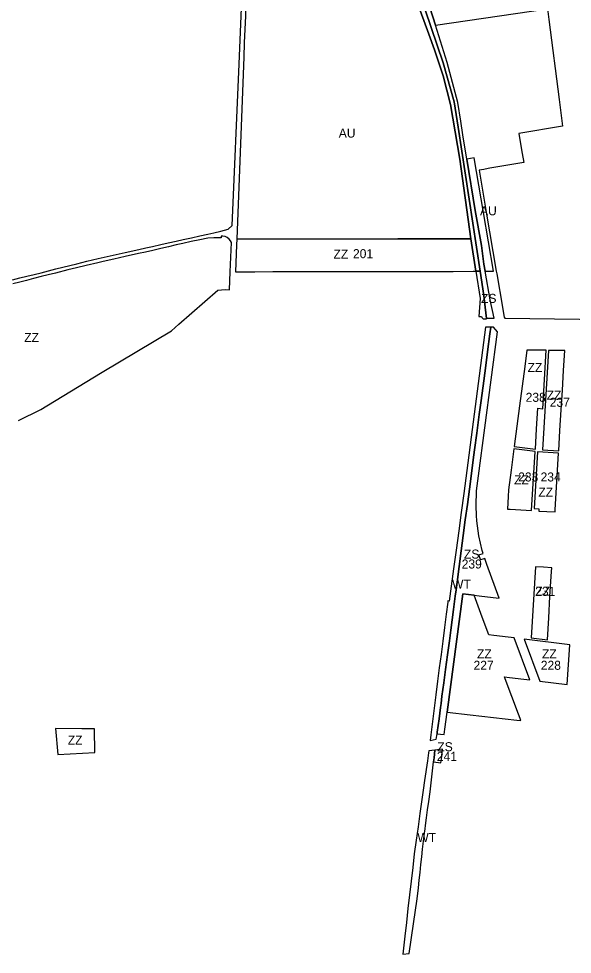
# Model space of a CAD drawing. Extents: x -521939 to -516426, y -1197857 to -1189551.
# Drawn here: x -519936 to -519323, y -1191680 to -1190643 of the extents above; entities that cross this region are included whole.
import ezdxf

# ---------------------------------------------------------------- set-up
doc = ezdxf.new("R2010")
doc.units = 0
for name, color, linetype in [('90640013', 7, 'Continuous'), ('90660013', 7, 'Continuous'), ('90660023', 7, 'Continuous'), ('90670013', 7, 'Continuous'), ('90670023', 7, 'Continuous'), ('90710013', 7, 'Continuous'), ('90750013', 7, 'Continuous'), ('ID_navrh', 7, 'Continuous')]:
    doc.layers.add(name, color=color, linetype=linetype)

msp = doc.modelspace()

# ---------------------------------------------------------------- linework, layer by layer
at = {"layer": '90640013'}
for points in [[(-519512.13, -1190554.9), (-519465.6, -1190691.56), (-519453.62, -1190734.65), (-519449.03, -1190762.69), (-519424.89, -1190922.71), (-519420.85, -1190949.46), (-519419.21, -1190962.53), (-519417.66, -1190974.95), (-519417.62, -1190974.6), (-519409.21, -1190974.7)], [(-519409.21, -1190974.7), (-519413.53, -1190954.2), (-519419.2, -1190922.7), (-519420.59, -1190914.95), (-519423.23, -1190894), (-519430.27, -1190855.42), (-519439.5, -1190798.18), (-519443.82, -1190771.36), (-519446.26, -1190756.2), (-519449.61, -1190735.43), (-519461.43, -1190691.22), (-519474.2, -1190649.71), (-519490.33, -1190599.63)], [(-519418.92, -1190984.59), (-519442.95, -1191169.26), (-519445.69, -1191190.31), (-519448.24, -1191210.54), (-519451.44, -1191231.94), (-519454.5, -1191252.76), (-519457.65, -1191277.52), (-519459.03, -1191288.5), (-519460.46, -1191288.31), (-519460.65, -1191289.8), (-519462.36, -1191303.03), (-519464.29, -1191317.96), (-519466.22, -1191332.83), (-519468.14, -1191347.66), (-519470.07, -1191362.61), (-519471.98, -1191377.42), (-519473.9, -1191392.31), (-519475.83, -1191407.23), (-519477.63, -1191422.05), (-519479.54, -1191436.95), (-519480.3, -1191443.11), (-519473.41, -1191441.72), (-519473.18, -1191440.03), (-519472.77, -1191437.09), (-519472.58, -1191435.69), (-519472.32, -1191433.7), (-519470.37, -1191418.91), (-519468.71, -1191406.36), (-519468.15, -1191402.09), (-519467.09, -1191394.09), (-519465.11, -1191379.15), (-519463.15, -1191364.31), (-519461, -1191348.01), (-519458.94, -1191332.49), (-519457.39, -1191320.76), (-519454.38, -1191298), (-519452.43, -1191283.22), (-519451.46, -1191275.9), (-519450.34, -1191267.46), (-519448.07, -1191250.27), (-519445.75, -1191232.74), (-519443.51, -1191215.75), (-519441.23, -1191198.47), (-519438.99, -1191181.55), (-519436.7, -1191164.25), (-519434.43, -1191147.07), (-519432.39, -1191131.65), (-519430.97, -1191120.9), (-519428.51, -1191102.27), (-519425.76, -1191081.47), (-519424.05, -1191068.52), (-519421.56, -1191049.69), (-519418.96, -1191030.07), (-519416.58, -1191012.09), (-519413.94, -1190992.07), (-519412.96, -1190984.66), (-519418.92, -1190984.59)], [(-519481.79, -1191510.66), (-519480.11, -1191500.2), (-519476.39, -1191466.96), (-519475.89, -1191462.49), (-519474.91, -1191453.7), (-519481.78, -1191454.44), (-519481.98, -1191456.8), (-519483.25, -1191465.69), (-519486.37, -1191487.58), (-519487.87, -1191498.12), (-519489.37, -1191508.66), (-519491.56, -1191524), (-519493.61, -1191538.9), (-519495.77, -1191553.8), (-519497.82, -1191568.74), (-519499.58, -1191583.93), (-519501.26, -1191598.96), (-519503.13, -1191614.19), (-519504.8, -1191629.42), (-519506.55, -1191644.93), (-519508.19, -1191660.16), (-519510.41, -1191680.24), (-519503.48, -1191679.19), (-519498.55, -1191646.53), (-519494.72, -1191618.59), (-519493.26, -1191606.37), (-519492.35, -1191598.05), (-519491.39, -1191589.35), (-519490.44, -1191580.74), (-519489.49, -1191572.1), (-519488.54, -1191563.47), (-519487.59, -1191554.84), (-519486.62, -1191546.07), (-519485.82, -1191540.95), (-519485.29, -1191537.48), (-519484.17, -1191528.9), (-519483.02, -1191520.08), (-519481.79, -1191510.66)]]:
    msp.add_lwpolyline(points, dxfattribs=at)
at = {"layer": '90660013'}
msp.add_lwpolyline([(-519424.76, -1190952.81), (-519426.07, -1190972.68), (-519423.35, -1190972.89), (-519423.05, -1190974.12), (-519421.6, -1190975.48), (-519417.75, -1190975.6), (-519417.58, -1190975.61), (-519417.66, -1190974.95), (-519419.21, -1190962.53), (-519420.85, -1190949.46), (-519424.89, -1190922.71), (-519429.49, -1190922.71), (-519424.76, -1190952.81)], dxfattribs=at)
at = {"layer": '90660023'}
for points in [[(-519461.41, -1191411.78), (-519444.02, -1191280.38), (-519431.59, -1191281.9), (-519426, -1191282.58), (-519410.34, -1191284.49), (-519403.63, -1191285.31), (-519417.54, -1191248.08), (-519419.67, -1191241.33), (-519421.98, -1191242.06), (-519424.44, -1191242.84), (-519424.56, -1191242.44), (-519426.25, -1191237.12), (-519421.48, -1191235.61), (-519422.56, -1191232.21), (-519426.21, -1191215.98), (-519428.47, -1191199.49), (-519428.77, -1191193.5), (-519429.31, -1191182.88), (-519428.73, -1191166.25), (-519426.73, -1191149.73), (-519405.56, -1190989.71), (-519409.91, -1190984.69), (-519411.43, -1190984.67), (-519412.96, -1190984.66), (-519413.94, -1190992.07), (-519416.58, -1191012.09), (-519418.96, -1191030.07), (-519421.56, -1191049.69), (-519424.05, -1191068.52), (-519425.76, -1191081.47), (-519428.51, -1191102.27), (-519430.97, -1191120.9), (-519432.39, -1191131.65), (-519434.43, -1191147.07), (-519436.7, -1191164.25), (-519438.99, -1191181.55), (-519441.23, -1191198.47), (-519443.51, -1191215.75), (-519445.75, -1191232.74), (-519448.07, -1191250.27), (-519450.34, -1191267.46), (-519451.46, -1191275.9), (-519452.43, -1191283.22), (-519454.38, -1191298), (-519457.39, -1191320.76), (-519458.94, -1191332.49), (-519461, -1191348.01), (-519463.15, -1191364.31), (-519465.11, -1191379.15), (-519467.09, -1191394.09), (-519468.15, -1191402.09), (-519468.71, -1191406.36), (-519470.37, -1191418.91), (-519472.32, -1191433.7), (-519472.58, -1191435.69), (-519468.64, -1191436.13), (-519464.69, -1191436.57), (-519463.91, -1191430.62), (-519461.41, -1191411.78)], [(-519476.39, -1191466.96), (-519468.24, -1191467.91), (-519467.73, -1191463.4), (-519466.53, -1191452.71), (-519474.91, -1191453.7), (-519475.89, -1191462.49), (-519476.39, -1191466.96)]]:
    msp.add_lwpolyline(points, dxfattribs=at)
at = {"layer": '90670013'}
for points in [[(-519936.67, -1191088.33), (-519911.75, -1191075.87), (-519854.19, -1191040.86), (-519843.69, -1191034.57), (-519767.01, -1190988.64), (-519758.76, -1190981.42), (-519715.58, -1190943.61), (-519711.51, -1190943.28), (-519707.45, -1190942.95), (-519702.46, -1190943.23), (-519701.74, -1190923.21), (-519700.57, -1190890.69), (-519701.34, -1190889.07), (-519703.03, -1190887.15), (-519705.1, -1190885.35), (-519707.32, -1190884.15), (-519710.16, -1190883.6), (-519711.68, -1190883.58), (-519711.68, -1190885.43), (-519720, -1190885.58), (-519726.78, -1190886.09), (-519735.59, -1190887.67), (-519745.1, -1190889.75), (-519754.32, -1190891.81), (-519761.88, -1190893.5), (-519770.26, -1190895.53), (-519778.8, -1190897.57), (-519787.54, -1190899.54), (-519795.54, -1190901.33), (-519803.46, -1190903.12), (-519818.3, -1190906.39), (-519830.75, -1190909.18), (-519842.5, -1190911.8), (-519848.52, -1190913.15), (-519861.35, -1190916.11), (-519872.14, -1190918.8), (-519881.75, -1190921.22), (-519895.36, -1190924.64), (-519903.58, -1190926.7), (-519911.36, -1190928.66), (-519919.76, -1190930.76), (-519927.66, -1190932.75), (-519935.17, -1190934.6), (-519942.63, -1190936.51)], [(-519851.93, -1191456.47), (-519852.18, -1191430.31), (-519866.4, -1191430.14), (-519895.29, -1191429.8), (-519892.88, -1191458.5), (-519851.93, -1191456.47)]]:
    msp.add_lwpolyline(points, dxfattribs=at)
at = {"layer": '90670023'}
for points in [[(-519429.49, -1190922.71), (-519435.15, -1190886.72), (-519516.08, -1190886.87), (-519694.59, -1190887.19), (-519694.83, -1190893.33), (-519695.96, -1190923.2), (-519695.95, -1190923.2), (-519692.95, -1190923.19), (-519674.43, -1190923.15), (-519654.53, -1190923.12), (-519634.52, -1190923.08), (-519614.52, -1190923.05), (-519594.53, -1190923.01), (-519574.53, -1190922.97), (-519554.53, -1190922.94), (-519534.53, -1190922.9), (-519514.53, -1190922.86), (-519494.53, -1190922.83), (-519474.53, -1190922.79), (-519454.53, -1190922.76), (-519432.53, -1190922.72), (-519429.49, -1190922.71)], [(-519387.1, -1191117.04), (-519363.6, -1191120.15), (-519362.23, -1191097.34), (-519360.86, -1191074.57), (-519355.39, -1191075.29), (-519351.49, -1191010.37), (-519372.96, -1191010.12), (-519375.36, -1191028.27), (-519378.24, -1191050.08), (-519381.13, -1191071.89), (-519384.11, -1191094.44), (-519387.1, -1191117.04)], [(-519337.67, -1191121.99), (-519336.3, -1191099.23), (-519334.93, -1191076.52), (-519333.61, -1191054.56), (-519332.29, -1191032.6), (-519330.96, -1191010.64), (-519330.96, -1191010.61), (-519339.73, -1191010.51), (-519348.98, -1191010.4), (-519355.64, -1191120.91), (-519337.67, -1191121.99)], [(-519387.43, -1191119.47), (-519390.57, -1191143.26), (-519393.46, -1191165.11), (-519393.76, -1191172.43), (-519394.33, -1191186.5), (-519391.65, -1191186.66), (-519379.67, -1191187.38), (-519367.7, -1191188.1), (-519363.75, -1191122.6), (-519387.43, -1191119.47)], [(-519359.71, -1191188.58), (-519350.73, -1191189.12), (-519341.74, -1191189.67), (-519341.6, -1191187.32), (-519339.71, -1191155.88), (-519337.82, -1191124.43), (-519361.27, -1191123.02), (-519365.06, -1191185.91), (-519359.57, -1191186.24), (-519359.71, -1191188.58)], [(-519350.27, -1191331.3), (-519348.8, -1191306.9), (-519347.39, -1191283.45), (-519345.71, -1191255.5), (-519345.47, -1191251.55), (-519354.45, -1191251.01), (-519363.44, -1191250.47), (-519368.17, -1191329.12), (-519350.27, -1191331.3)], [(-519461.41, -1191411.78), (-519435.74, -1191414.66), (-519410, -1191417.54), (-519384.16, -1191420.43), (-519379.67, -1191420.94), (-519380.54, -1191418.61), (-519382.3, -1191413.9), (-519389.59, -1191394.38), (-519396.88, -1191374.85), (-519397.79, -1191372.41), (-519392.19, -1191373.11), (-519376.52, -1191375.05), (-519369.81, -1191375.88), (-519387.2, -1191329.32), (-519393.91, -1191328.5), (-519409.56, -1191326.59), (-519415.16, -1191325.91), (-519422.47, -1191306.33), (-519431.59, -1191281.9), (-519444.02, -1191280.38), (-519461.41, -1191411.78)], [(-519328.22, -1191381.04), (-519325.56, -1191336.84), (-519376.01, -1191330.68), (-519358.62, -1191377.27), (-519328.22, -1191381.04)]]:
    msp.add_lwpolyline(points, dxfattribs=at)
at = {"layer": '90710013'}
for points in [[(-519429.49, -1190922.71), (-519424.89, -1190922.71), (-519449.03, -1190762.69), (-519453.62, -1190734.65), (-519465.6, -1190691.56), (-519512.13, -1190554.9)], [(-519491.09, -1190633.4), (-519481.62, -1190659.8), (-519475.51, -1190677.19), (-519465.89, -1190705.97), (-519457.49, -1190737.73), (-519447.4, -1190798.17), (-519435.15, -1190886.72), (-519429.49, -1190922.71)]]:
    msp.add_lwpolyline(points, dxfattribs=at)
at = {"layer": '90750013'}
for points in [[(-519294.71, -1190586.4), (-519349.34, -1190592.5), (-519354.17, -1190593), (-519490.33, -1190599.63), (-519474.2, -1190649.71), (-519350.06, -1190631.54), (-519348.65, -1190643.36), (-519337.21, -1190732.05), (-519333.43, -1190761.83), (-519381.92, -1190770.01), (-519378.78, -1190788), (-519378.08, -1190792.18), (-519376.41, -1190801.97), (-519413.98, -1190808.49), (-519415.74, -1190808.8), (-519420.82, -1190809.69), (-519425.9, -1190810.59)], [(-519435.15, -1190886.72), (-519447.4, -1190798.17), (-519457.49, -1190737.73), (-519465.89, -1190705.97), (-519475.51, -1190677.19), (-519481.62, -1190659.8), (-519491.09, -1190633.4), (-519495.04, -1190621.79), (-519499.5, -1190609.21), (-519502.67, -1190599.7), (-519684.13, -1190608.58), (-519684.13, -1190614.39), (-519684.52, -1190626.67), (-519685, -1190639.32), (-519686.23, -1190669.35), (-519686.8, -1190685.4), (-519687.84, -1190713.61), (-519694.59, -1190887.19), (-519516.08, -1190886.87), (-519435.15, -1190886.72)], [(-519943.05, -1190932.07), (-519934.89, -1190930.13), (-519927.39, -1190928.23), (-519919.3, -1190926.24), (-519911.52, -1190924.24), (-519903.31, -1190922.21), (-519895.15, -1190920.15), (-519871.99, -1190914.33), (-519860.73, -1190911.52), (-519848.19, -1190908.66), (-519818.11, -1190901.93), (-519803.05, -1190898.55), (-519795.35, -1190896.85), (-519787.9, -1190895.13), (-519778.65, -1190893.08), (-519770.59, -1190891.25), (-519761.74, -1190889.28), (-519753.88, -1190887.53), (-519744.82, -1190885.5), (-519735.48, -1190883.39), (-519726.71, -1190881.45), (-519720.01, -1190879.91), (-519712.1, -1190878.14), (-519704.17, -1190875.86), (-519699.53, -1190872.03), (-519691.85, -1190693.04), (-519689.17, -1190630.58)], [(-519419.2, -1190922.7), (-519414.66, -1190922.69), (-519410.13, -1190922.68), (-519421.19, -1190857.53), (-519431.49, -1190796.83), (-519435.5, -1190797.51), (-519439.5, -1190798.18), (-519430.27, -1190855.42), (-519423.23, -1190894), (-519420.59, -1190914.95), (-519419.2, -1190922.7)], [(-519425.9, -1190810.59), (-519418.01, -1190857.09), (-519406.86, -1190922.67), (-519406.39, -1190925.44), (-519400.11, -1190962.39), (-519398.51, -1190971.76), (-519398.04, -1190973.7), (-519397.29, -1190974.84), (-519259.53, -1190976.44)]]:
    msp.add_lwpolyline(points, dxfattribs=at)

# ---------------------------------------------------------------- texts
at = {"layer": '90640013'}
for rotation, p in [(0, (-519455.9, -1191274.59)), (360, (-519494.39, -1191555.74))]:
    msp.add_text('WT', height=10, rotation=rotation, dxfattribs=at).set_placement(p)
at = {"layer": '90660013'}
msp.add_text('ZS', height=10, rotation=360, dxfattribs=at).set_placement((-519423.77, -1190957.74))
at = {"layer": '90660023'}
for rotation, p in [(360, (-519442.69, -1191241.34)), (0, (-519472.25, -1191455.03))]:
    msp.add_text('ZS', height=10, rotation=rotation, dxfattribs=at).set_placement(p)
at = {"layer": '90670013'}
for rotation, p in [(360, (-519930.09, -1191001.05)), (0, (-519881.84, -1191447.6))]:
    msp.add_text('ZZ', height=10, rotation=rotation, dxfattribs=at).set_placement(p)
at = {"layer": '90670023'}
for p in [(-519587.35, -1190908.57), (-519372.19, -1191034.39), (-519351.08, -1191065.26), (-519387.21, -1191159.14), (-519360.27, -1191172.75), (-519363.57, -1191282.51), (-519428.33, -1191352.17), (-519356.34, -1191352.17)]:
    msp.add_text('ZZ', height=10, rotation=0, dxfattribs=at).set_placement(p)
at = {"layer": '90750013'}
for rotation, p in [(0, (-519581.5, -1190774.43)), (360, (-519424.93, -1190860.66))]:
    msp.add_text('AU', height=10, rotation=rotation, dxfattribs=at).set_placement(p)
at = {"layer": 'ID_navrh'}
msp.add_text('201', height=10, dxfattribs=at).set_placement((-519565.74, -1190908.17))
for s, rotation, p in [('238', 360, (-519374.36, -1191067.49)), ('237', 0, (-519347.67, -1191073.01)), ('233', 0, (-519382.64, -1191155.82)), ('234', 360, (-519357.79, -1191155.82)), ('239', 0, (-519445.26, -1191252.36)), ('231', 0, (-519363.82, -1191282.73)), ('227', 0, (-519432.12, -1191364.7)), ('228', 360, (-519357.57, -1191364.7)), ('241', 0, (-519472.74, -1191465.69))]:
    msp.add_text(s, height=10, rotation=rotation, dxfattribs=at).set_placement(p)

doc.saveas('drawing.dxf')
